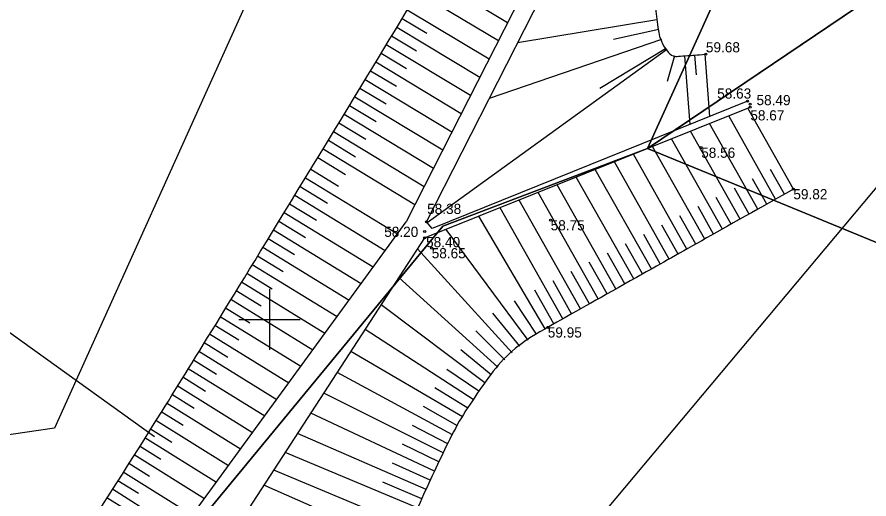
# Model space of a CAD drawing. Extents: x 616607 to 617499, y 408385 to 409695.
# Drawn here: x 616937.6 to 616979.44, y 408591.17 to 408614.87 of the extents above; entities that cross this region are included whole.
import ezdxf

# ---------------------------------------------------------------- set-up
doc = ezdxf.new("R2010")
doc.units = 0
for name, color, linetype in [('DREN_VADP_####_####_#', 7, 'Continuous'), ('GEOD_ELEM_####_####_#', 7, 'Continuous'), ('HIDG_GRAV_####_####_#', 7, 'Continuous'), ('RAMI_UZMR_####_####_#', 7, 'Continuous'), ('RELJ_AATZ_####_TKST_#', 7, 'Continuous'), ('RELJ_ELEM_####_####_#', 7, 'Continuous'), ('RELJ_NOGA_####_####_#', 7, 'Continuous'), ('ROBZ_IERR_####_####_#', 7, 'Continuous'), ('ROBZ_UZMR_####_####_#', 7, 'Continuous')]:
    doc.layers.add(name, color=color, linetype=linetype)

# ---------------------------------------------------------------- blocks, each defined once
blk = doc.blocks.new('PKT')
at = {"layer": 'RELJ_ELEM_####_####_#'}
blk.add_circle((0, 0), 0.05, dxfattribs=at)
blk = doc.blocks.new('KRUSTS')
at = {"layer": 'GEOD_ELEM_####_####_#'}
for p, q in [((0, 1.5), (0, 0)), ((-1.5, 0), (0, 0)), ((0, 0), (0, -1.5)), ((0, 0), (1.5, 0))]:
    blk.add_line(p, q, dxfattribs=at)

msp = doc.modelspace()

# ---------------------------------------------------------------- linework, layer by layer
at = {"layer": 'DREN_VADP_####_####_#'}
msp.add_lwpolyline([(616944.351, 408594.236), (616924.897, 408608.204)], dxfattribs=at)
at = {"layer": 'HIDG_GRAV_####_####_#'}
for points in [[(616957.708, 408604.801), (616964.717, 408618.582), (616997.814, 408672.816), (617082.506, 408751.106), (617088.497, 408760.889), (617116.937, 408835.934), (617137.451, 408884.548), (617152.78, 408924.733), (617163.79, 408955.542), (617160.997, 408956.152), (617115.742, 408836.043), (617088.001, 408760.943), (617081.506, 408751.106), (616997.147, 408673.705), (616963.717, 408618.582), (616956.708, 408604.801)], [(616973.482, 408610.73), (616957.996, 408604.469), (616957.708, 408604.801)], [(616957.621, 408604.01), (616973.613, 408610.435)], [(616768.796, 408535.775), (616917.84, 408577.602), (616920.619, 408579.054), (616921.042, 408581.087), (616920.637, 408583.341), (616920.568, 408585.209), (616921.519, 408586.112), (616924.38, 408586.959), (616926.829, 408586.782), (616930.695, 408584.537), (616934.052, 408583.069), (616937.754, 408584.05), (616942.21, 408586.817), (616945.351, 408589.192), (616956.708, 408604.801)], [(616957.621, 408604.01), (616947.332, 408588.16), (616947.6, 408585.931), (616945.208, 408582.089), (616935.727, 408576.737), (616858.974, 408555.268)]]:
    msp.add_lwpolyline(points, dxfattribs=at)
at = {"layer": 'RAMI_UZMR_####_####_#'}
for points in [[(617191.828, 409115.62), (617145.545, 408952.8), (617072.809, 408766.141), (616965.332, 408652.076), (616939.432, 408594.661), (616924.839, 408592.467), (616706.433, 408526.081), (616666.426, 408467.691)], [(616666.426, 408467.691), (616675.529, 408457.882), (616687.228, 408463.356), (616723.888, 408465.775), (616753.554, 408507.232), (616948.282, 408568.831), (616981.528, 408608.531), (617014.563, 408672.892), (617101.571, 408748.246), (617213.472, 409074.039)]]:
    msp.add_lwpolyline(points, dxfattribs=at)
at = {"layer": 'RELJ_NOGA_####_####_#'}
for p, q in [((616957.799, 408616.946), (616961.694, 408614.605)), ((616957.284, 408616.089), (616961.24, 408613.712)), ((616956.769, 408615.232), (616960.784, 408612.816)), ((616956.431, 408614.662), (616956.431, 408614.662)), ((616956.511, 408614.803), (616957.725, 408614.073)), ((616969.023, 408614.742), (616962.183, 408613.6)), ((616956.172, 408614.234), (616956.173, 408614.234)), ((616956.253, 408614.375), (616960.33, 408611.922)), ((616969.116, 408614.251), (616966.891, 408613.771)), ((616955.914, 408613.806), (616955.915, 408613.806)), ((616955.995, 408613.947), (616957.227, 408613.204)), ((616969.247, 408613.769), (616960.796, 408610.873)), ((616955.656, 408613.378), (616955.656, 408613.378)), ((616955.737, 408613.518), (616959.874, 408611.026)), ((616969.493, 408613.251), (616957.746, 408604.757)), ((616969.452, 408613.314), (616966.233, 408611.358)), ((616969.493, 408613.251), (616969.494, 408613.251)), ((616955.397, 408612.95), (616955.398, 408612.95)), ((616955.479, 408613.09), (616956.729, 408612.336)), ((616969.888, 408612.958), (616969.529, 408611.709)), ((616969.81, 408612.976), (616969.809, 408612.975)), ((616969.888, 408612.958), (616969.888, 408612.958)), ((616970.304, 408612.957), (616970.304, 408612.957)), ((616970.385, 408612.963), (616970.385, 408612.964)), ((616970.385, 408612.963), (616970.643, 408609.582)), ((616970.802, 408612.995), (616970.802, 408612.994)), ((616970.883, 408613.001), (616970.883, 408613.002)), ((616970.883, 408613.001), (616970.957, 408612.035)), ((616971.301, 408613.033), (616971.301, 408613.033)), ((616971.382, 408613.039), (616971.382, 408613.04)), ((616971.382, 408613.039), (616971.616, 408609.975)), ((616955.138, 408612.522), (616955.139, 408612.522)), ((616955.22, 408612.662), (616959.418, 408610.13)), ((616954.88, 408612.094), (616954.88, 408612.094)), ((616954.962, 408612.234), (616956.23, 408611.468)), ((616954.621, 408611.667), (616954.621, 408611.666)), ((616954.703, 408611.806), (616958.962, 408609.233)), ((616954.362, 408611.239), (616954.363, 408611.238)), ((616954.445, 408611.378), (616955.731, 408610.6)), ((616954.103, 408610.811), (616954.103, 408610.811)), ((616954.186, 408610.951), (616958.506, 408608.336)), ((616953.843, 408610.384), (616953.844, 408610.383)), ((616953.927, 408610.523), (616955.233, 408609.733)), ((616975.731, 408606.41), (616973.491, 408610.386)), ((616953.584, 408609.956), (616953.584, 408609.956)), ((616953.668, 408610.095), (616958.05, 408607.438)), ((616974.86, 408605.919), (616972.555, 408610.01)), ((616953.325, 408609.529), (616953.326, 408609.528)), ((616953.408, 408609.668), (616954.733, 408608.865)), ((616973.989, 408605.428), (616971.619, 408609.634)), ((616953.065, 408609.101), (616953.065, 408609.101)), ((616953.149, 408609.24), (616957.593, 408606.54)), ((616973.118, 408604.937), (616970.683, 408609.258)), ((616952.805, 408608.674), (616952.806, 408608.674)), ((616952.89, 408608.813), (616954.232, 408607.997)), ((616972.246, 408604.446), (616969.747, 408608.882)), ((616952.546, 408608.247), (616952.546, 408608.247)), ((616952.63, 408608.386), (616957.138, 408605.646)), ((616971.375, 408603.955), (616968.811, 408608.506)), ((616952.286, 408607.82), (616952.287, 408607.819)), ((616952.37, 408607.958), (616953.732, 408607.129)), ((616969.633, 408602.973), (616966.939, 408607.753)), ((616970.504, 408603.464), (616967.875, 408608.13)), ((616952.025, 408607.393), (616953.391, 408606.561)), ((616952.025, 408607.393), (616952.026, 408607.393)), ((616952.11, 408607.531), (616952.111, 408607.531)), ((616968.762, 408602.482), (616966.003, 408607.377)), ((616975.296, 408606.164), (616974.614, 408607.374)), ((616951.765, 408606.966), (616956.281, 408604.213)), ((616951.765, 408606.966), (616951.766, 408606.965)), ((616967.89, 408601.991), (616965.067, 408607.001)), ((616974.424, 408605.673), (616973.723, 408606.918)), ((616951.505, 408606.539), (616952.849, 408605.719)), ((616951.505, 408606.539), (616951.505, 408606.539)), ((616967.019, 408601.501), (616964.131, 408606.625)), ((616951.244, 408606.112), (616955.688, 408603.399)), ((616951.244, 408606.112), (616951.245, 408606.112)), ((616966.148, 408601.01), (616963.195, 408606.249)), ((616973.553, 408605.182), (616972.833, 408606.461)), ((616975.296, 408606.164), (616975.295, 408606.164)), ((616975.731, 408606.41), (616975.731, 408606.41)), ((616950.984, 408605.686), (616952.306, 408604.877)), ((616950.984, 408605.686), (616950.984, 408605.685)), ((616965.277, 408600.519), (616962.26, 408605.873)), ((616972.682, 408604.691), (616971.942, 408606.005)), ((616974.424, 408605.673), (616974.424, 408605.673)), ((616974.86, 408605.919), (616974.86, 408605.92)), ((616950.723, 408605.259), (616955.096, 408602.585)), ((616950.723, 408605.259), (616950.724, 408605.258)), ((616964.406, 408600.028), (616961.324, 408605.497)), ((616971.811, 408604.201), (616971.051, 408605.548)), ((616973.989, 408605.428), (616973.988, 408605.429)), ((616950.462, 408604.832), (616951.763, 408604.036)), ((616950.462, 408604.832), (616950.462, 408604.832)), ((616963.535, 408599.536), (616960.275, 408605.076)), ((616970.94, 408603.71), (616970.161, 408605.092)), ((616973.118, 408604.937), (616973.117, 408604.938)), ((616973.553, 408605.182), (616973.553, 408605.183)), ((616950.201, 408604.406), (616954.502, 408601.769)), ((616950.201, 408604.406), (616950.202, 408604.405)), ((616962.7, 408598.986), (616958.672, 408604.432)), ((616970.068, 408603.219), (616969.27, 408604.636)), ((616972.246, 408604.446), (616972.246, 408604.447)), ((616972.682, 408604.691), (616972.682, 408604.692)), ((616949.94, 408603.98), (616951.22, 408603.195)), ((616949.94, 408603.98), (616949.94, 408603.98)), ((616969.197, 408602.728), (616968.379, 408604.179)), ((616971.811, 408604.201), (616971.811, 408604.201)), ((616949.678, 408603.553), (616953.91, 408600.955)), ((616949.678, 408603.553), (616949.679, 408603.553)), ((616968.326, 408602.237), (616967.489, 408603.723)), ((616970.94, 408603.71), (616970.939, 408603.71)), ((616971.375, 408603.955), (616971.375, 408603.956)), ((616961.925, 408598.355), (616957.275, 408603.476)), ((616967.455, 408601.746), (616966.598, 408603.266)), ((616970.068, 408603.219), (616970.068, 408603.219)), ((616970.504, 408603.464), (616970.503, 408603.465)), ((616949.417, 408603.127), (616950.676, 408602.354)), ((616949.417, 408603.127), (616949.417, 408603.127)), ((616966.584, 408601.255), (616965.708, 408602.81)), ((616969.197, 408602.728), (616969.197, 408602.728)), ((616969.633, 408602.973), (616969.632, 408602.974)), ((616949.155, 408602.701), (616953.318, 408600.142)), ((616949.155, 408602.701), (616949.156, 408602.701)), ((616965.712, 408600.764), (616964.817, 408602.353)), ((616968.762, 408602.482), (616968.761, 408602.483)), ((616948.893, 408602.275), (616950.132, 408601.514)), ((616948.893, 408602.275), (616948.893, 408602.275)), ((616961.216, 408597.65), (616956.359, 408602.064)), ((616964.841, 408600.273), (616963.926, 408601.897)), ((616967.89, 408601.991), (616967.89, 408601.992)), ((616968.326, 408602.237), (616968.326, 408602.237)), ((616948.631, 408601.85), (616952.726, 408599.328)), ((616948.631, 408601.85), (616948.632, 408601.849)), ((616967.019, 408601.501), (616967.019, 408601.501)), ((616967.455, 408601.746), (616967.455, 408601.746)), ((616948.369, 408601.424), (616949.587, 408600.673)), ((616948.369, 408601.424), (616948.369, 408601.424)), ((616963.97, 408599.782), (616963.036, 408601.44)), ((616966.584, 408601.255), (616966.583, 408601.255)), ((616948.106, 408600.998), (616952.134, 408598.514)), ((616948.106, 408600.998), (616948.107, 408600.998)), ((616960.578, 408596.881), (616955.483, 408600.715)), ((616963.11, 408599.272), (616962.03, 408600.921)), ((616965.712, 408600.764), (616965.712, 408600.764)), ((616966.148, 408601.01), (616966.147, 408601.01)), ((616947.844, 408600.573), (616949.042, 408599.833)), ((616947.844, 408600.573), (616947.844, 408600.573)), ((616962.304, 408598.68), (616960.969, 408600.307)), ((616964.841, 408600.273), (616964.841, 408600.273)), ((616965.277, 408600.519), (616965.276, 408600.52)), ((616947.581, 408600.147), (616951.541, 408597.7)), ((616947.581, 408600.147), (616947.582, 408600.147)), ((616964.406, 408600.028), (616964.405, 408600.029)), ((616947.318, 408599.722), (616948.496, 408598.994)), ((616947.318, 408599.722), (616947.318, 408599.722)), ((616960.009, 408596.059), (616954.704, 408599.515)), ((616961.562, 408598.011), (616960.142, 408599.444)), ((616963.535, 408599.536), (616963.534, 408599.537)), ((616963.97, 408599.782), (616963.97, 408599.783)), ((616947.055, 408599.297), (616950.949, 408596.886)), ((616947.055, 408599.297), (616947.056, 408599.296)), ((616962.7, 408598.986), (616962.699, 408598.987)), ((616963.11, 408599.272), (616963.11, 408599.272)), ((616946.792, 408598.872), (616947.95, 408598.154)), ((616946.792, 408598.872), (616946.792, 408598.872)), ((616962.304, 408598.68), (616962.304, 408598.681)), ((616946.528, 408598.447), (616950.356, 408596.071)), ((616946.528, 408598.447), (616946.529, 408598.446)), ((616959.484, 408595.208), (616953.991, 408598.417)), ((616960.888, 408597.273), (616959.397, 408598.507)), ((616961.925, 408598.355), (616961.924, 408598.356)), ((616946.264, 408598.022), (616947.403, 408597.315)), ((616946.264, 408598.022), (616946.265, 408598.022)), ((616961.562, 408598.011), (616961.562, 408598.011)), ((616946, 408597.597), (616949.764, 408595.257)), ((616946, 408597.597), (616946.001, 408597.597)), ((616958.996, 408594.335), (616953.321, 408597.386)), ((616960.286, 408596.475), (616958.716, 408597.547)), ((616961.216, 408597.65), (616961.215, 408597.651)), ((616945.736, 408597.173), (616946.856, 408596.476)), ((616945.736, 408597.173), (616945.737, 408597.173)), ((616960.578, 408596.881), (616960.577, 408596.882)), ((616960.888, 408597.273), (616960.888, 408597.273)), ((616945.472, 408596.748), (616949.171, 408594.442)), ((616945.472, 408596.748), (616945.473, 408596.748)), ((616959.742, 408595.636), (616958.123, 408596.635)), ((616960.286, 408596.475), (616960.286, 408596.475)), ((616945.208, 408596.324), (616946.308, 408595.638)), ((616945.208, 408596.324), (616945.208, 408596.324)), ((616958.538, 408593.446), (616952.667, 408596.378)), ((616960.009, 408596.059), (616960.008, 408596.059)), ((616944.943, 408595.9), (616948.581, 408593.632)), ((616944.943, 408595.9), (616944.944, 408595.899)), ((616959.236, 408594.774), (616957.562, 408595.713)), ((616959.742, 408595.636), (616959.741, 408595.636)), ((616944.678, 408595.476), (616945.76, 408594.8)), ((616944.678, 408595.476), (616944.678, 408595.476)), ((616958.103, 408592.546), (616952.025, 408595.39)), ((616959.484, 408595.208), (616959.483, 408595.208)), ((616944.413, 408595.052), (616947.988, 408592.817)), ((616944.413, 408595.052), (616944.414, 408595.051)), ((616958.763, 408593.892), (616957.029, 408594.783)), ((616959.236, 408594.774), (616959.235, 408594.774)), ((616944.148, 408594.628), (616945.211, 408593.962)), ((616944.148, 408594.628), (616944.148, 408594.628)), ((616957.689, 408591.636), (616951.376, 408594.39)), ((616943.883, 408594.204), (616947.395, 408592.002)), ((616943.883, 408594.204), (616943.883, 408594.204)), ((616958.996, 408594.335), (616958.995, 408594.336)), ((616943.617, 408593.781), (616944.661, 408593.125)), ((616943.617, 408593.781), (616943.617, 408593.78)), ((616958.318, 408592.997), (616956.527, 408593.865)), ((616958.763, 408593.892), (616958.763, 408593.893)), ((616943.351, 408593.357), (616946.804, 408591.189)), ((616943.351, 408593.357), (616943.352, 408593.357)), ((616957.295, 408590.716), (616950.768, 408593.454)), ((616958.538, 408593.446), (616958.537, 408593.447)), ((616943.085, 408592.934), (616944.112, 408592.288)), ((616943.085, 408592.934), (616943.085, 408592.934)), ((616957.893, 408592.092), (616956.039, 408592.938)), ((616958.318, 408592.997), (616958.318, 408592.997)), ((616942.819, 408592.511), (616946.211, 408590.375)), ((616942.819, 408592.511), (616942.819, 408592.51)), ((616956.909, 408589.794), (616950.212, 408592.597)), ((616958.103, 408592.546), (616958.102, 408592.546)), ((616942.552, 408592.088), (616943.561, 408591.451)), ((616942.552, 408592.088), (616942.552, 408592.087)), ((616956.516, 408588.874), (616949.726, 408591.848)), ((616957.49, 408591.177), (616955.563, 408591.997)), ((616957.893, 408592.092), (616957.892, 408592.092)), ((616942.285, 408591.665), (616945.62, 408589.562)), ((616942.285, 408591.665), (616942.286, 408591.664)), ((616957.689, 408591.636), (616957.688, 408591.636)), ((616942.018, 408591.242), (616943.006, 408590.618)), ((616942.018, 408591.242), (616942.019, 408591.242)), ((616957.49, 408591.177), (616957.49, 408591.177))]:
    msp.add_line(p, q, dxfattribs=at)
for points in [[(616952.11, 408607.531), (616956.151, 408614.166), (616960.13, 408620.838), (616964.128, 408627.499), (616969.357, 408636.209), (616974.533, 408644.951), (616979.755, 408653.666), (616982.367, 408658.027), (616985.018, 408662.364), (616987.709, 408666.677), (616989.056, 408668.838), (616990.438, 408670.976), (616991.835, 408673.105), (616992.534, 408674.172), (616993.243, 408675.231), (616993.95, 408676.293), (616994.657, 408677.356), (616995.377, 408678.409), (616996.104, 408679.46), (616998.164, 408682.436), (617000.493, 408685.215), (617003.037, 408687.806), (617005.59, 408690.406), (617008.236, 408692.879), (617011.016, 408695.214), (617013.812, 408697.562), (617016.632, 408699.88), (617019.423, 408702.233), (617020.817, 408703.408), (617022.221, 408704.57), (617023.595, 408705.77), (617024.962, 408706.965), (617026.3, 408708.194), (617027.642, 408709.417), (617031.797, 408713.202), (617035.92, 408717.024), (617040.083, 408720.8), (617044.243, 408724.572), (617048.471, 408728.267), (617052.642, 408732.025), (617056.824, 408735.794), (617060.981, 408739.59), (617065.093, 408743.436), (617067.159, 408745.369), (617069.191, 408747.335), (617071.208, 408749.318), (617072.22, 408750.314), (617073.221, 408751.32), (617074.226, 408752.322), (617075.234, 408753.328), (617076.23, 408754.338), (617077.212, 408755.375), (617081.698, 408760.112), (617084.989, 408765.985), (617087.243, 408772.093), (617089.541, 408778.321), (617091.528, 408784.634), (617093.829, 408790.846), (617099.646, 408806.547), (617105.384, 408822.279), (617111.331, 408837.932), (617116.967, 408852.766), (617122.795, 408867.526), (617128.465, 408882.346), (617134.52, 408898.17), (617140.109, 408914.165), (617146.15, 408930), (617147.203, 408932.762), (617148.413, 408935.46), (617149.608, 408938.162), (617150.805, 408940.87), (617152.218, 408943.437), (617153.491, 408946.151), (617155.134, 408949.654), (617156.252, 408953.338), (617157.386, 408956.937), (617157.388, 408956.942), (617157.376, 408956.956), (617157.382, 408956.955), (617158.587, 408956.687), (617159.792, 408956.42), (617160.997, 408956.152)], [(617163.79, 408955.542), (617165.45, 408955.194), (617167.11, 408954.846), (617168.77, 408954.498), (617168.913, 408954.468), (617169.034, 408954.324), (617169.074, 408954.183), (617169.128, 408953.99), (617169.08, 408953.773), (617169.007, 408953.587), (617168.835, 408953.148), (617168.665, 408952.708), (617168.483, 408952.272), (617167.485, 408949.894), (617166.495, 408947.512), (617165.486, 408945.138), (617164.477, 408942.762), (617163.444, 408940.395), (617162.435, 408938.019), (617160.416, 408933.265), (617158.392, 408928.513), (617156.542, 408923.692), (617150.713, 408908.507), (617144.931, 408893.305), (617139.111, 408878.118), (617136.201, 408870.523), (617133.294, 408862.928), (617130.378, 408855.336), (617127.463, 408847.744), (617124.504, 408840.168), (617121.547, 408832.592), (617116.624, 408819.98), (617111.621, 408807.399), (617106.663, 408794.801), (617101.918, 408782.741), (617097.386, 408770.604), (617092.68, 408758.522), (617091.748, 408756.128), (617090.638, 408753.8), (617089.099, 408751.701), (617087.891, 408750.055), (617086.512, 408748.607), (617085.075, 408747.191), (617082.094, 408744.254), (617079.138, 408741.303), (617076.078, 408738.453), (617073.02, 408735.605), (617069.97, 408732.751), (617066.861, 408729.96), (617060.644, 408724.38), (617054.349, 408718.89), (617048.124, 408713.32), (617041.902, 408707.753), (617035.717, 408702.149), (617029.576, 408696.491), (617026.506, 408693.662), (617023.563, 408690.704), (617020.596, 408687.763), (617017.626, 408684.818), (617014.683, 408681.855), (617011.931, 408678.697), (617008.517, 408674.776), (617005.359, 408670.661), (617002.288, 408666.476), (616999.318, 408662.428), (616996.36, 408658.374), (616993.424, 408654.302), (616990.492, 408650.235), (616987.575, 408646.161), (616984.691, 408642.059), (616983.288, 408640.063), (616981.951, 408638.02), (616980.703, 408635.922), (616979.453, 408633.819), (616978.237, 408631.7), (616977.033, 408629.572), (616975.83, 408627.444), (616974.65, 408625.305), (616973.452, 408623.174), (616972.259, 408621.052), (616970.984, 408618.974), (616969.729, 408616.893), (616969.613, 408616.701), (616969.41, 408616.592), (616969.29, 408616.383), (616968.995, 408615.872), (616968.948, 408615.291), (616969.02, 408614.761), (616969.09, 408614.251), (616969.19, 408613.683), (616969.493, 408613.251)], [(616969.493, 408613.251), (616969.617, 408613.075), (616969.842, 408612.922), (616970.056, 408612.938), (616970.514, 408612.973), (616970.971, 408613.008), (616971.429, 408613.043)], [(616975.731, 408606.41), (616971.71, 408604.144), (616967.689, 408601.878), (616963.668, 408599.612), (616962.341, 408598.864), (616961.192, 408597.791), (616960.311, 408596.511), (616959.39, 408595.173), (616958.675, 408593.776), (616958.002, 408592.329), (616957.302, 408590.825), (616956.736, 408589.272), (616956.015, 408587.778), (616955.313, 408586.324), (616954.582, 408584.882), (616953.626, 408583.572), (616952.496, 408582.025), (616951.261, 408580.593), (616950.022, 408579.143), (616948.785, 408577.695), (616947.537, 408576.278), (616946.22, 408574.895), (616945.626, 408574.271), (616944.957, 408573.742), (616944.225, 408573.278), (616943.451, 408572.788), (616942.648, 408572.387), (616941.804, 408572.051), (616941, 408571.73), (616940.2, 408571.414), (616939.368, 408571.187), (616938.69, 408571.002), (616938.005, 408570.852), (616937.329, 408570.663), (616918.615, 408565.441), (616899.903, 408560.204), (616881.253, 408554.75), (616874.57, 408552.796), (616867.991, 408550.484), (616861.269, 408548.669), (616855.483, 408547.106), (616849.688, 408545.577), (616843.9, 408544.023), (616838.111, 408542.469), (616832.323, 408540.916), (616826.537, 408539.352), (616816.497, 408536.637), (616806.51, 408533.737), (616796.541, 408530.774), (616791.553, 408529.292), (616786.584, 408527.751), (616781.609, 408526.226), (616776.622, 408524.697), (616771.656, 408523.11), (616766.688, 408521.515), (616762.607, 408520.204), (616758.677, 408518.521), (616754.775, 408516.687), (616750.921, 408514.875), (616747.341, 408512.653), (616743.915, 408510.109), (616740.341, 408507.454), (616736.942, 408504.677), (616733.801, 408501.555), (616732.131, 408499.895), (616730.49, 408498.223), (616728.926, 408496.468), (616728.114, 408495.556), (616727.318, 408494.632), (616726.518, 408493.709), (616725.695, 408492.76), (616724.91, 408491.864), (616724.122, 408490.803), (616723.665, 408490.187), (616723.18, 408489.459), (616723.332, 408488.764), (616723.537, 408487.829), (616723.949, 408486.896), (616724.213, 408485.954), (616724.975, 408483.236), (616725.742, 408480.486), (616726.381, 408477.738), (616726.631, 408476.667), (616726.554, 408475.507), (616726.221, 408474.429), (616726.043, 408473.855), (616725.77, 408473.346), (616725.415, 408472.86), (616725.226, 408472.602), (616725.032, 408472.37), (616724.813, 408472.14), (616724.582, 408471.898), (616724.347, 408471.683), (616724.071, 408471.48), (616723.783, 408471.268), (616723.475, 408471.091), (616723.13, 408471.039), (616722.812, 408470.991), (616722.494, 408470.986), (616722.176, 408470.982), (616721.543, 408470.975), (616720.901, 408471.154), (616720.278, 408471.02), (616716.569, 408470.219), (616712.93, 408469.339), (616709.261, 408468.478), (616707.424, 408468.047), (616705.589, 408467.613), (616703.751, 408467.182), (616701.927, 408466.754), (616700.076, 408466.424), (616698.236, 408466.115), (616695.42, 408465.64), (616692.315, 408465.565), (616689.691, 408467.073), (616684.319, 408470.158), (616679.892, 408473.486), (616675.008, 408476.777), (616674.831, 408476.896), (616674.652, 408477.012), (616674.483, 408477.14), (616674.175, 408477.376), (616674.46, 408477.978), (616674.696, 408478.288), (616675.427, 408479.251), (616676.165, 408480.2), (616676.939, 408481.135), (616677.893, 408482.289), (616678.812, 408483.429), (616679.848, 408484.532), (616681.078, 408485.839), (616682.698, 408486.726), (616684.412, 408487.237), (616686.183, 408487.764), (616687.958, 408488.143), (616689.768, 408488.401), (616691.642, 408488.668), (616693.528, 408488.826), (616695.398, 408489.116), (616696.323, 408489.26), (616697.239, 408489.444), (616698.155, 408489.647), (616699.054, 408489.848), (616699.912, 408490.166), (616700.785, 408490.476), (616703.122, 408491.305), (616705.613, 408491.942), (616707.248, 408494.043), (616707.429, 408494.275), (616707.474, 408494.537), (616707.552, 408494.798), (616707.628, 408495.051), (616707.711, 408495.3), (616707.761, 408495.559), (616707.86, 408496.068), (616707.943, 408496.577), (616707.977, 408497.092), (616708.044, 408498.12), (616708.108, 408499.147), (616708.168, 408500.175), (616708.254, 408501.63), (616708.34, 408503.085), (616708.414, 408504.54), (616708.488, 408505.998), (616708.403, 408507.461), (616708.436, 408508.92), (616708.468, 408510.38), (616708.539, 408511.837), (616708.686, 408513.293), (616708.76, 408514.026), (616708.887, 408514.749), (616709.039, 408515.47), (616709.116, 408515.834), (616709.208, 408516.193), (616709.297, 408516.554), (616709.387, 408516.92), (616709.487, 408517.278), (616709.619, 408517.635), (616710.681, 408520.51), (616712.959, 408522.898), (616715.736, 408524.335), (616718.688, 408525.863), (616721.668, 408526.887), (616724.792, 408527.643), (616730.078, 408528.922), (616735.359, 408530.207), (616740.655, 408531.436), (616749.901, 408533.581), (616759.244, 408535.317), (616768.413, 408537.779), (616798.7, 408545.91), (616828.618, 408555.288), (616858.746, 408563.964), (616877.646, 408569.406), (616896.581, 408574.731), (616915.501, 408580.089), (616916.131, 408580.267), (616916.803, 408580.127), (616917.44, 408580.402), (616917.832, 408580.571), (616918.181, 408580.992), (616918.136, 408581.394), (616918.071, 408581.969), (616918.005, 408582.544), (616917.94, 408583.119), (616917.87, 408583.733), (616917.799, 408584.347), (616917.73, 408584.96), (616917.674, 408585.454), (616917.97, 408585.948), (616918.384, 408586.3), (616918.906, 408586.742), (616919.445, 408586.959), (616920.02, 408587.218), (616920.568, 408587.465), (616921.093, 408587.698), (616921.676, 408587.899), (616922.792, 408588.284), (616923.918, 408588.529), (616925.044, 408588.565), (616925.938, 408588.594), (616926.854, 408588.454), (616927.734, 408588.123), (616928.677, 408587.768), (616929.526, 408587.359), (616930.432, 408586.999), (616931.324, 408586.645), (616932.223, 408586.313), (616933.127, 408585.998), (616933.97, 408585.704), (616934.935, 408585.706), (616935.807, 408585.922), (616937.564, 408586.355), (616939.443, 408587.201), (616940.422, 408588.724), (616944.438, 408594.972), (616948.27, 408601.228), (616952.11, 408607.531)]]:
    msp.add_open_spline(points, degree=3, dxfattribs=at)
at = {"layer": 'ROBZ_IERR_####_####_#'}
for points in [[(617055.284, 408797.783), (617087.528, 408757.04), (616999.181, 408676.019), (616968.565, 408608.405), (616958.517, 408604.593), (616940.576, 408582.801), (616889.795, 408568.012), (616805.459, 408543.657), (616730.494, 408522.344), (616717.135, 408556.579)], [(617001.984, 408630.998), (616968.565, 408608.405), (616999.181, 408676.019), (617087.528, 408757.04), (617055.515, 408797.492)], [(616997.177, 408596.644), (616974.837, 408605.827), (616968.565, 408608.405), (616998.907, 408628.918)]]:
    msp.add_lwpolyline(points, dxfattribs=at)
at = {"layer": 'ROBZ_UZMR_####_####_#'}
msp.add_lwpolyline([(616704.998, 408460.626), (616695.309, 408466.84), (616688.046, 408471.498), (616708.653, 408488.203), (616730.494, 408522.344), (616805.459, 408543.657), (616889.795, 408568.012), (616940.576, 408582.801), (616958.517, 408604.593), (616968.565, 408608.405), (616974.837, 408605.827), (616993.227, 408598.268)], dxfattribs=at)

# ---------------------------------------------------------------- block references
at = {"layer": 'GEOD_ELEM_####_####_#'}
msp.add_blockref('KRUSTS', (616950, 408600), dxfattribs=at)
at = {"layer": 'RELJ_ELEM_####_####_#'}
for p in [(616971.429, 408613.043), (616973.482, 408610.73), (616973.609, 408610.592), (616973.613, 408610.435), (616971.204, 408608.45), (616975.731, 408606.41), (616957.708, 408604.801), (616963.81, 408604.881), (616957.621, 408604.01), (616957.622, 408604.324), (616957.967, 408603.509), (616963.668, 408599.612)]:
    msp.add_blockref('PKT', p, dxfattribs=at)

# ---------------------------------------------------------------- texts
at = {"layer": 'RELJ_AATZ_####_TKST_#'}
for s, p in [('59.68', (616971.435, 408613.134)), ('58.63', (616971.989, 408610.862)), ('58.49', (616973.921, 408610.537)), ('58.67', (616973.617, 408609.788)), ('58.56', (616971.204, 408607.95)), ('59.82', (616975.731, 408605.91)), ('58.38', (616957.743, 408605.187)), ('58.75', (616963.81, 408604.381)), ('58.20', (616955.635, 408604.06)), ('58.40', (616957.691, 408603.554)), ('58.65', (616957.967, 408603.009)), ('59.95', (616963.668, 408599.112))]:
    msp.add_text(s, height=0.5, dxfattribs=at).set_placement(p)

doc.saveas('drawing.dxf')
